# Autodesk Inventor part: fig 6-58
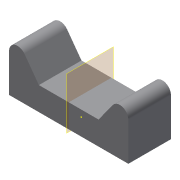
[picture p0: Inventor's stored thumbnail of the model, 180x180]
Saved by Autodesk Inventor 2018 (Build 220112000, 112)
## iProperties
Created: 2011-07
Part Number: fig 6-58
Material: Generic
Document SubType Name: Modeling
Designer: CadCim
Density: 1 g/cm^3
Appearance: Default
Author: CadCim
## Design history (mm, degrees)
sketch "Sketch1"
  geometry: 1 further point
sketch "Sketch2"
  geometry: L1 (3, -4)-(17, -4); L2 (17, -4)-(17, 7); L3 (17, 7)-(14, 7); L4 (14, 7)-(10, 1.5); L5 (10, 1.5)-(3, 1.5); L6 (3, -4)-(-11, -4); L7 (-11, -4)-(-11, 7); L8 (-11, 7)-(-8, 7); L9 (-8, 7)-(-4, 1.5); L10 (-4, 1.5)-(3, 1.5); 1 further point
  constraints: 20 end point, 2 parallel, 1 perpendicular
extrude "Extrusion1" new body sketch "Sketch2" distance "d0" = 10; taper "d1" = 0 deg
fillet "Fillet1" dims "d2" = 2
workplane "Work Plane1"
mirror "Mirror1"
body "Solid1"
